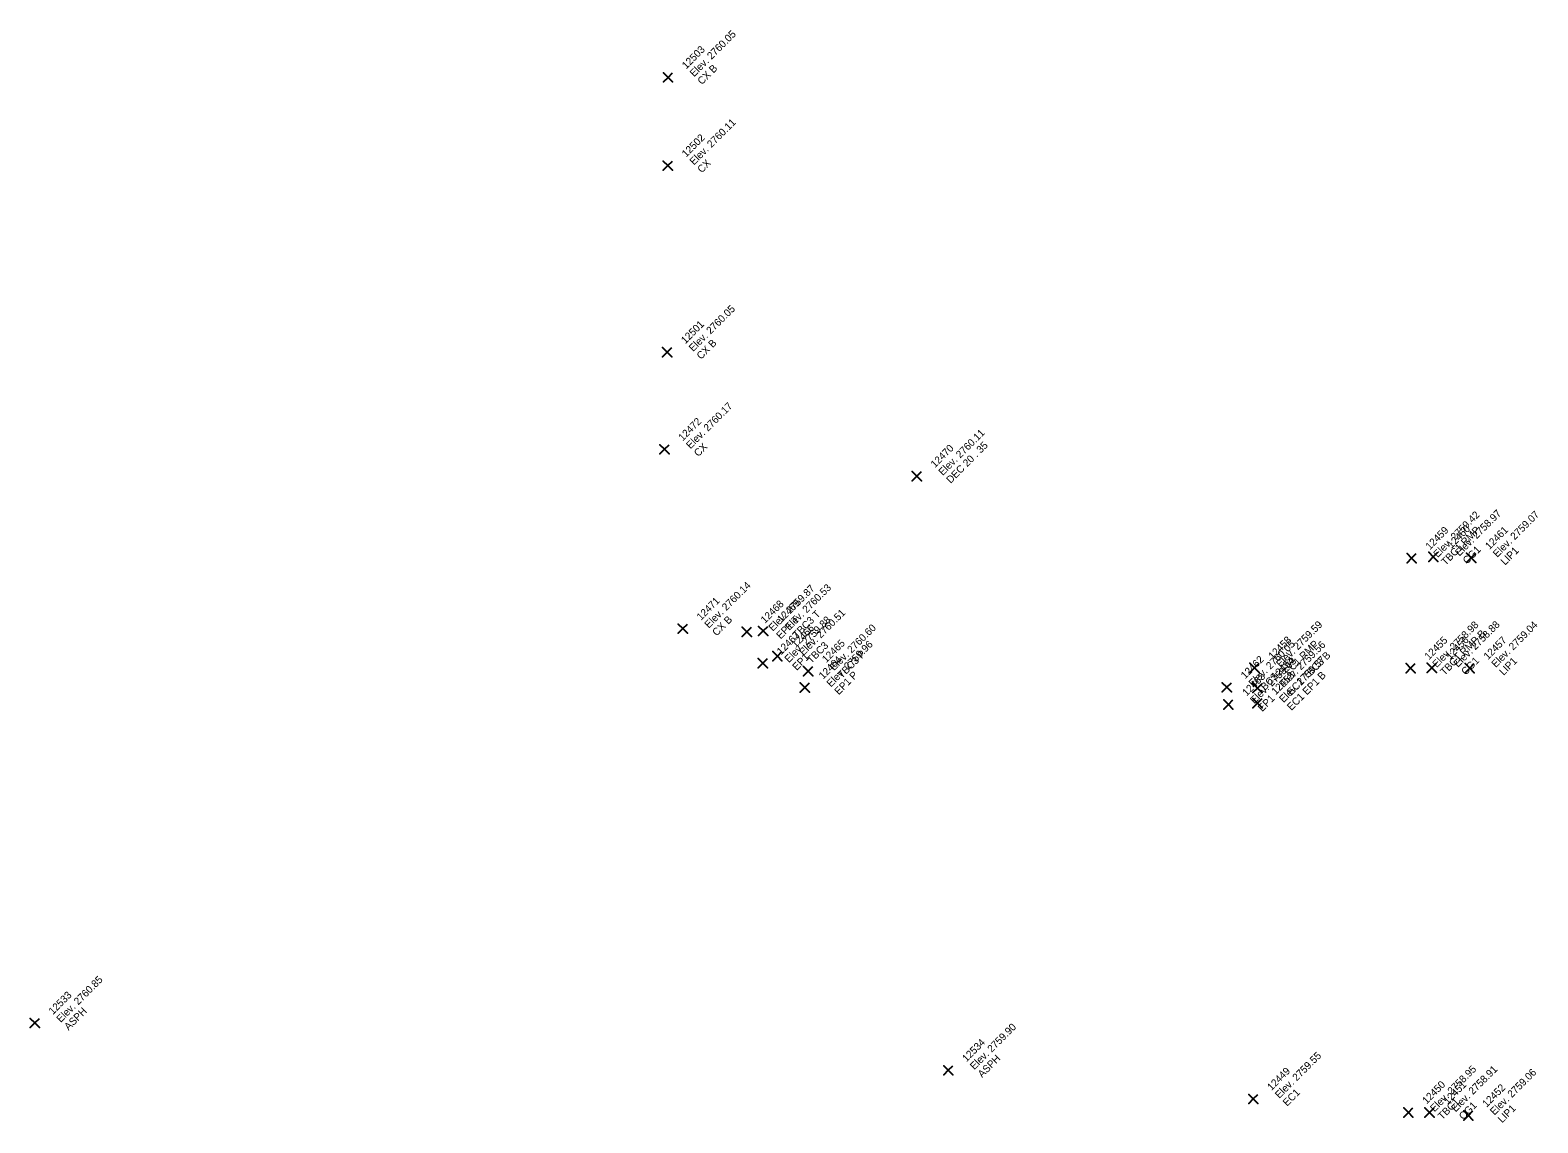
# Model space of a CAD drawing. Extents: x 2493999 to 2503109, y 700767 to 706646.
# Drawn here: x 2502204.19 to 2502253.35, y 702296.53 to 702332.14 of the extents above; entities that cross this region are included whole.
import ezdxf

# ---------------------------------------------------------------- set-up
doc = ezdxf.new("R2010")
doc.units = 0
doc.layers.add('ALG_CL_BLUE_Horiz', color=7, linetype='Continuous')
doc.layers.add('DES_SURFACE_Existing-Ground', color=7, linetype='Continuous')

msp = doc.modelspace()

# ---------------------------------------------------------------- linework, layer by layer
at = {"layer": 'ALG_CL_BLUE_Horiz'}
for points in [[(2502224.989, 702330.605), (2502224.839, 702330.755), (2502224.989, 702330.605), (2502224.839, 702330.455), (2502224.989, 702330.605), (2502225.139, 702330.455), (2502224.989, 702330.605), (2502225.139, 702330.755)], [(2502224.986, 702327.728), (2502224.836, 702327.878), (2502224.986, 702327.728), (2502224.836, 702327.578), (2502224.986, 702327.728), (2502225.136, 702327.578), (2502224.986, 702327.728), (2502225.136, 702327.878)], [(2502224.962, 702321.649), (2502224.812, 702321.799), (2502224.962, 702321.649), (2502224.812, 702321.499), (2502224.962, 702321.649), (2502225.112, 702321.499), (2502224.962, 702321.649), (2502225.112, 702321.799)], [(2502224.874, 702318.48), (2502224.724, 702318.63), (2502224.874, 702318.48), (2502224.724, 702318.33), (2502224.874, 702318.48), (2502225.024, 702318.33), (2502224.874, 702318.48), (2502225.024, 702318.63)], [(2502233.101, 702317.607), (2502232.951, 702317.757), (2502233.101, 702317.607), (2502232.951, 702317.457), (2502233.101, 702317.607), (2502233.251, 702317.457), (2502233.101, 702317.607), (2502233.251, 702317.757)], [(2502249.236, 702314.933), (2502249.086, 702315.083), (2502249.236, 702314.933), (2502249.086, 702314.783), (2502249.236, 702314.933), (2502249.386, 702314.783), (2502249.236, 702314.933), (2502249.386, 702315.083)], [(2502249.942, 702314.978), (2502249.792, 702315.128), (2502249.942, 702314.978), (2502249.792, 702314.828), (2502249.942, 702314.978), (2502250.092, 702314.828), (2502249.942, 702314.978), (2502250.092, 702315.128)], [(2502251.18, 702314.943), (2502251.03, 702315.093), (2502251.18, 702314.943), (2502251.03, 702314.793), (2502251.18, 702314.943), (2502251.33, 702314.793), (2502251.18, 702314.943), (2502251.33, 702315.093)], [(2502225.472, 702312.634), (2502225.322, 702312.784), (2502225.472, 702312.634), (2502225.322, 702312.484), (2502225.472, 702312.634), (2502225.622, 702312.484), (2502225.472, 702312.634), (2502225.622, 702312.784)], [(2502227.559, 702312.533), (2502227.409, 702312.683), (2502227.559, 702312.533), (2502227.409, 702312.383), (2502227.559, 702312.533), (2502227.709, 702312.383), (2502227.559, 702312.533), (2502227.709, 702312.683)], [(2502228.095, 702312.56), (2502227.945, 702312.71), (2502228.095, 702312.56), (2502227.945, 702312.41), (2502228.095, 702312.56), (2502228.245, 702312.41), (2502228.095, 702312.56), (2502228.245, 702312.71)], [(2502228.083, 702311.51), (2502227.933, 702311.66), (2502228.083, 702311.51), (2502227.933, 702311.36), (2502228.083, 702311.51), (2502228.233, 702311.36), (2502228.083, 702311.51), (2502228.233, 702311.66)], [(2502228.556, 702311.738), (2502228.406, 702311.888), (2502228.556, 702311.738), (2502228.406, 702311.588), (2502228.556, 702311.738), (2502228.706, 702311.588), (2502228.556, 702311.738), (2502228.706, 702311.888)], [(2502244.111, 702311.356), (2502243.961, 702311.506), (2502244.111, 702311.356), (2502243.961, 702311.206), (2502244.111, 702311.356), (2502244.261, 702311.206), (2502244.111, 702311.356), (2502244.261, 702311.506)], [(2502249.204, 702311.347), (2502249.054, 702311.497), (2502249.204, 702311.347), (2502249.054, 702311.197), (2502249.204, 702311.347), (2502249.354, 702311.197), (2502249.204, 702311.347), (2502249.354, 702311.497)], [(2502249.894, 702311.357), (2502249.744, 702311.507), (2502249.894, 702311.357), (2502249.744, 702311.207), (2502249.894, 702311.357), (2502250.044, 702311.207), (2502249.894, 702311.357), (2502250.044, 702311.507)], [(2502251.13, 702311.347), (2502250.98, 702311.497), (2502251.13, 702311.347), (2502250.98, 702311.197), (2502251.13, 702311.347), (2502251.28, 702311.197), (2502251.13, 702311.347), (2502251.28, 702311.497)], [(2502229.557, 702311.25), (2502229.407, 702311.4), (2502229.557, 702311.25), (2502229.407, 702311.1), (2502229.557, 702311.25), (2502229.707, 702311.1), (2502229.557, 702311.25), (2502229.707, 702311.4)], [(2502229.452, 702310.713), (2502229.302, 702310.863), (2502229.452, 702310.713), (2502229.302, 702310.563), (2502229.452, 702310.713), (2502229.602, 702310.563), (2502229.452, 702310.713), (2502229.602, 702310.863)], [(2502243.213, 702310.722), (2502243.063, 702310.872), (2502243.213, 702310.722), (2502243.063, 702310.572), (2502243.213, 702310.722), (2502243.363, 702310.572), (2502243.213, 702310.722), (2502243.363, 702310.872)], [(2502244.211, 702310.698), (2502244.061, 702310.848), (2502244.211, 702310.698), (2502244.061, 702310.548), (2502244.211, 702310.698), (2502244.361, 702310.548), (2502244.211, 702310.698), (2502244.361, 702310.848)], [(2502243.26, 702310.165), (2502243.11, 702310.315), (2502243.26, 702310.165), (2502243.11, 702310.015), (2502243.26, 702310.165), (2502243.41, 702310.015), (2502243.26, 702310.165), (2502243.41, 702310.315)], [(2502244.211, 702310.205), (2502244.061, 702310.355), (2502244.211, 702310.205), (2502244.061, 702310.055), (2502244.211, 702310.205), (2502244.361, 702310.055), (2502244.211, 702310.205), (2502244.361, 702310.355)], [(2502204.341, 702299.781), (2502204.191, 702299.931), (2502204.341, 702299.781), (2502204.191, 702299.631), (2502204.341, 702299.781), (2502204.491, 702299.631), (2502204.341, 702299.781), (2502204.491, 702299.931)], [(2502234.128, 702298.238), (2502233.978, 702298.388), (2502234.128, 702298.238), (2502233.978, 702298.088), (2502234.128, 702298.238), (2502234.278, 702298.088), (2502234.128, 702298.238), (2502234.278, 702298.388)], [(2502244.074, 702297.304), (2502243.924, 702297.454), (2502244.074, 702297.304), (2502243.924, 702297.154), (2502244.074, 702297.304), (2502244.224, 702297.154), (2502244.074, 702297.304), (2502244.224, 702297.454)], [(2502249.13, 702296.864), (2502248.98, 702297.014), (2502249.13, 702296.864), (2502248.98, 702296.714), (2502249.13, 702296.864), (2502249.28, 702296.714), (2502249.13, 702296.864), (2502249.28, 702297.014)], [(2502249.817, 702296.86), (2502249.667, 702297.01), (2502249.817, 702296.86), (2502249.667, 702296.71), (2502249.817, 702296.86), (2502249.967, 702296.71), (2502249.817, 702296.86), (2502249.967, 702297.01)], [(2502251.087, 702296.761), (2502250.937, 702296.911), (2502251.087, 702296.761), (2502250.937, 702296.611), (2502251.087, 702296.761), (2502251.237, 702296.611), (2502251.087, 702296.761), (2502251.237, 702296.911)]]:
    msp.add_lwpolyline(points, dxfattribs=at)

# ---------------------------------------------------------------- texts
at = {"layer": 'DES_SURFACE_Existing-Ground'}
for s, p in [('Elev. 2760.05', (2502225.838, 702330.605)), ('12503', (2502225.583, 702330.86)), ('CX B', (2502226.092, 702330.35)), ('Elev. 2760.11', (2502225.835, 702327.728)), ('12502', (2502225.58, 702327.983)), ('CX', (2502226.089, 702327.473)), ('Elev. 2760.05', (2502225.811, 702321.649)), ('12501', (2502225.556, 702321.904)), ('CX B', (2502226.065, 702321.394)), ('Elev. 2760.17', (2502225.723, 702318.48)), ('12472', (2502225.468, 702318.735)), ('Elev. 2760.11', (2502233.95, 702317.607)), ('CX', (2502225.977, 702318.225)), ('12470', (2502233.695, 702317.862)), ('DEC 20 . 35', (2502234.204, 702317.352)), ('Elev. 2759.42', (2502250.085, 702314.933)), ('Elev. 2758.97', (2502250.791, 702314.978)), ('Elev. 2759.07', (2502252.029, 702314.943)), ('12459', (2502249.83, 702315.188)), ('TBC1 RMP', (2502250.339, 702314.678)), ('12460', (2502250.536, 702315.233)), ('12461', (2502251.774, 702315.198)), ('CG1', (2502251.045, 702314.723)), ('LIP1', (2502252.283, 702314.688)), ('Elev. 2760.14', (2502226.321, 702312.634)), ('Elev. 2759.87', (2502228.408, 702312.533)), ('Elev. 2760.53', (2502228.944, 702312.56)), ('12471', (2502226.066, 702312.889)), ('12468', (2502228.153, 702312.788)), ('12469', (2502228.689, 702312.815)), ('CX B', (2502226.575, 702312.379)), ('EP1 T', (2502228.662, 702312.278)), ('Elev. 2759.88', (2502228.932, 702311.51)), ('TBC3 T', (2502229.198, 702312.305)), ('Elev. 2760.51', (2502229.405, 702311.738)), ('Elev. 2759.59', (2502244.96, 702311.356)), ('Elev. 2758.88', (2502250.743, 702311.357)), ('12467', (2502228.677, 702311.765)), ('12466', (2502229.15, 702311.993)), ('Elev. 2760.60', (2502230.406, 702311.25)), ('Elev. 2758.98', (2502250.053, 702311.347)), ('TBC1 RMP B', (2502250.307, 702311.092)), ('12456', (2502250.488, 702311.612)), ('12457', (2502251.724, 702311.602)), ('Elev. 2759.04', (2502251.979, 702311.347)), ('TBC3', (2502229.659, 702311.483)), ('12465', (2502230.151, 702311.505)), ('Elev. 2759.96', (2502230.301, 702310.713)), ('TBC3 P', (2502230.66, 702310.995)), ('Elev. 2760.05', (2502244.062, 702310.722)), ('12458', (2502244.705, 702311.611)), ('Elev. 2759.56', (2502245.06, 702310.698)), ('EC1 RMP', (2502245.214, 702311.101)), ('12455', (2502249.798, 702311.602)), ('EP1', (2502229.186, 702311.255)), ('12464', (2502230.046, 702310.968)), ('12462', (2502243.807, 702310.977)), ('Elev. 2759.63', (2502244.109, 702310.165)), ('12454', (2502244.805, 702310.953)), ('Elev. 2759.57', (2502245.06, 702310.205)), ('EC1 TBC3 B', (2502245.314, 702310.443)), ('CG1', (2502250.997, 702311.102)), ('LIP1', (2502252.233, 702311.092)), ('EP1 P', (2502230.555, 702310.458)), ('12463', (2502243.854, 702310.42)), ('TBC3', (2502244.316, 702310.467)), ('12453', (2502244.805, 702310.46)), ('EC1 EP1 B', (2502245.314, 702309.95)), ('EP1', (2502244.363, 702309.91)), ('Elev. 2760.85', (2502205.19, 702299.781)), ('12533', (2502204.935, 702300.036)), ('ASPH', (2502205.444, 702299.526)), ('Elev. 2759.90', (2502234.977, 702298.238)), ('12534', (2502234.722, 702298.493)), ('ASPH', (2502235.231, 702297.983)), ('Elev. 2759.55', (2502244.923, 702297.304)), ('12449', (2502244.668, 702297.559)), ('Elev. 2758.95', (2502249.979, 702296.864)), ('Elev. 2758.91', (2502250.666, 702296.86)), ('Elev. 2759.06', (2502251.936, 702296.761)), ('12450', (2502249.724, 702297.119)), ('12451', (2502250.411, 702297.115)), ('12452', (2502251.681, 702297.016)), ('EC1', (2502245.177, 702297.049)), ('TBC1', (2502250.233, 702296.609)), ('CG1', (2502250.92, 702296.605)), ('LIP1', (2502252.19, 702296.506))]:
    msp.add_text(s, height=0.24, rotation=45, dxfattribs=at).set_placement(p)

doc.saveas('drawing.dxf')
